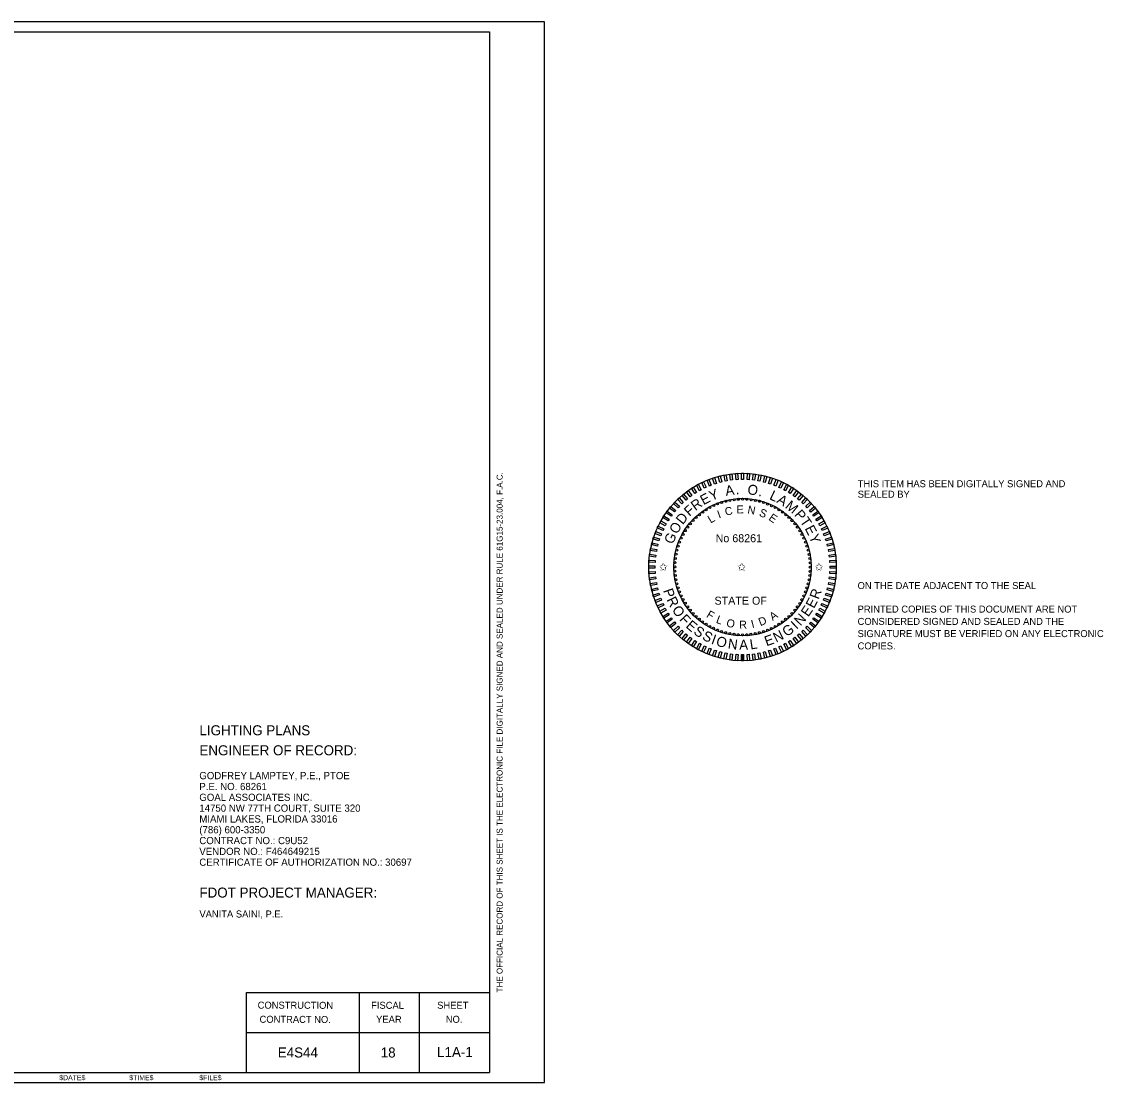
# Model space of a CAD drawing. Extents: x -820.2 to -798.1, y -2199.1 to -2182.2.
# Drawn here: x -808.95 to -798.14, y -2199.12 to -2188.52 of the extents above; entities that cross this region are included whole.
import ezdxf

# ---------------------------------------------------------------- set-up
doc = ezdxf.new("R2010")
doc.units = 0
for name, color, linetype in [('Logo_dp', 7, 'Continuous'), ('NonPlottingEle_dp', 7, 'Continuous'), ('PlotBorder_dp', 7, 'Continuous'), ('SheetBorder_dp', 7, 'Continuous'), ('SheetLines_dp', 7, 'Continuous'), ('TextLabel', 7, 'Continuous'), ('TextMinor', 7, 'Continuous'), ('TextMisc', 7, 'Continuous'), ('TextNotes', 7, 'Continuous')]:
    doc.layers.add(name, color=color, linetype=linetype)

msp = doc.modelspace()

# ---------------------------------------------------------------- linework, layer by layer
at = {"layer": 'Logo_dp'}
for p, q in [((-801.759, -2194.911), (-801.759, -2194.849)), ((-801.749, -2194.911), (-801.749, -2194.849)), ((-801.739, -2194.911), (-801.739, -2194.848))]:
    msp.add_line(p, q, dxfattribs=at)
for points in [[(-801.849, -2193.104), (-801.869, -2193.107), (-801.876, -2193.045), (-801.856, -2193.042)], [(-801.794, -2193.1), (-801.814, -2193.101), (-801.818, -2193.039), (-801.798, -2193.037)], [(-801.739, -2193.098), (-801.759, -2193.098), (-801.759, -2193.036), (-801.739, -2193.036)], [(-801.684, -2193.101), (-801.704, -2193.1), (-801.7, -2193.037), (-801.68, -2193.039)], [(-801.629, -2193.107), (-801.649, -2193.104), (-801.641, -2193.042), (-801.621, -2193.045)], [(-802.162, -2193.202), (-802.179, -2193.212), (-802.209, -2193.157), (-802.192, -2193.147)], [(-802.112, -2193.177), (-802.131, -2193.186), (-802.157, -2193.13), (-802.139, -2193.121)], [(-802.062, -2193.156), (-802.08, -2193.164), (-802.103, -2193.106), (-802.085, -2193.098)], [(-802.01, -2193.138), (-802.029, -2193.144), (-802.048, -2193.085), (-802.029, -2193.079)], [(-801.957, -2193.123), (-801.976, -2193.128), (-801.992, -2193.068), (-801.972, -2193.063)], [(-801.903, -2193.112), (-801.923, -2193.116), (-801.934, -2193.055), (-801.915, -2193.051)], [(-801.575, -2193.116), (-801.595, -2193.112), (-801.583, -2193.051), (-801.563, -2193.055)], [(-801.522, -2193.129), (-801.541, -2193.124), (-801.526, -2193.063), (-801.506, -2193.068)], [(-801.469, -2193.144), (-801.488, -2193.138), (-801.469, -2193.079), (-801.45, -2193.085)], [(-801.417, -2193.164), (-801.436, -2193.156), (-801.413, -2193.098), (-801.394, -2193.106)], [(-801.367, -2193.186), (-801.385, -2193.178), (-801.359, -2193.121), (-801.341, -2193.13)], [(-801.319, -2193.212), (-801.336, -2193.202), (-801.306, -2193.147), (-801.288, -2193.157)], [(-802.299, -2193.293), (-802.314, -2193.306), (-802.354, -2193.258), (-802.339, -2193.245)], [(-802.255, -2193.26), (-802.271, -2193.271), (-802.308, -2193.221), (-802.292, -2193.209)], [(-802.209, -2193.229), (-802.226, -2193.24), (-802.26, -2193.187), (-802.243, -2193.177)], [(-801.272, -2193.24), (-801.289, -2193.229), (-801.255, -2193.177), (-801.238, -2193.187)], [(-801.226, -2193.272), (-801.243, -2193.26), (-801.206, -2193.209), (-801.19, -2193.221)], [(-801.183, -2193.306), (-801.199, -2193.293), (-801.159, -2193.245), (-801.144, -2193.258)], [(-802.417, -2193.408), (-802.43, -2193.423), (-802.478, -2193.384), (-802.465, -2193.368)], [(-802.38, -2193.367), (-802.394, -2193.382), (-802.439, -2193.339), (-802.425, -2193.324)], [(-802.341, -2193.329), (-802.355, -2193.343), (-802.398, -2193.297), (-802.383, -2193.283)], [(-801.143, -2193.343), (-801.157, -2193.329), (-801.115, -2193.283), (-801.1, -2193.297)], [(-801.104, -2193.382), (-801.118, -2193.367), (-801.072, -2193.324), (-801.059, -2193.339)], [(-801.068, -2193.424), (-801.081, -2193.408), (-801.033, -2193.368), (-801.02, -2193.384)], [(-802.482, -2193.496), (-802.493, -2193.513), (-802.546, -2193.48), (-802.535, -2193.463)], [(-802.451, -2193.451), (-802.463, -2193.467), (-802.513, -2193.431), (-802.501, -2193.414)], [(-801.035, -2193.467), (-801.047, -2193.451), (-800.996, -2193.414), (-800.985, -2193.431)], [(-801.005, -2193.513), (-801.016, -2193.496), (-800.963, -2193.463), (-800.952, -2193.48)], [(-802.536, -2193.592), (-802.545, -2193.61), (-802.601, -2193.583), (-802.593, -2193.565)], [(-802.511, -2193.543), (-802.521, -2193.561), (-802.575, -2193.531), (-802.566, -2193.513)], [(-800.977, -2193.561), (-800.987, -2193.543), (-800.932, -2193.513), (-800.923, -2193.531)], [(-800.953, -2193.61), (-800.961, -2193.592), (-800.905, -2193.565), (-800.896, -2193.584)], [(-802.578, -2193.693), (-802.584, -2193.713), (-802.644, -2193.693), (-802.637, -2193.674)], [(-802.559, -2193.642), (-802.566, -2193.661), (-802.624, -2193.638), (-802.617, -2193.619)], [(-800.932, -2193.661), (-800.939, -2193.642), (-800.881, -2193.619), (-800.874, -2193.638)], [(-800.914, -2193.713), (-800.92, -2193.694), (-800.86, -2193.674), (-800.854, -2193.694)], [(-802.607, -2193.8), (-802.61, -2193.819), (-802.672, -2193.808), (-802.668, -2193.788)], [(-802.594, -2193.746), (-802.599, -2193.766), (-802.659, -2193.75), (-802.654, -2193.731)], [(-800.899, -2193.766), (-800.904, -2193.746), (-800.843, -2193.731), (-800.838, -2193.75)], [(-800.888, -2193.82), (-800.891, -2193.8), (-800.83, -2193.788), (-800.826, -2193.808)], [(-802.622, -2193.908), (-802.623, -2193.929), (-802.685, -2193.925), (-802.684, -2193.904)], [(-802.616, -2193.854), (-802.618, -2193.874), (-802.68, -2193.866), (-802.678, -2193.846)], [(-800.88, -2193.874), (-800.882, -2193.854), (-800.82, -2193.846), (-800.818, -2193.866)], [(-800.875, -2193.929), (-800.876, -2193.909), (-800.814, -2193.905), (-800.813, -2193.925)], [(-802.624, -2193.963), (-802.624, -2193.984), (-802.686, -2193.984), (-802.686, -2193.963)], [(-802.623, -2194.018), (-802.622, -2194.038), (-802.684, -2194.042), (-802.685, -2194.022)], [(-800.876, -2194.039), (-800.875, -2194.018), (-800.813, -2194.022), (-800.814, -2194.043)], [(-800.874, -2193.984), (-800.874, -2193.964), (-800.812, -2193.964), (-800.812, -2193.984)], [(-802.618, -2194.073), (-802.616, -2194.093), (-802.678, -2194.101), (-802.68, -2194.081)], [(-802.61, -2194.127), (-802.607, -2194.147), (-802.668, -2194.159), (-802.672, -2194.139)], [(-800.891, -2194.147), (-800.888, -2194.128), (-800.826, -2194.139), (-800.83, -2194.159)], [(-800.882, -2194.093), (-800.88, -2194.073), (-800.818, -2194.081), (-800.82, -2194.101)], [(-802.599, -2194.181), (-802.594, -2194.201), (-802.655, -2194.216), (-802.66, -2194.197)], [(-802.584, -2194.234), (-802.578, -2194.253), (-802.637, -2194.273), (-802.644, -2194.254)], [(-800.92, -2194.254), (-800.914, -2194.234), (-800.854, -2194.254), (-800.861, -2194.273)], [(-800.904, -2194.201), (-800.899, -2194.181), (-800.838, -2194.197), (-800.844, -2194.217)], [(-802.566, -2194.286), (-802.559, -2194.305), (-802.617, -2194.328), (-802.624, -2194.309)], [(-802.545, -2194.337), (-802.536, -2194.355), (-802.593, -2194.382), (-802.602, -2194.363)], [(-800.962, -2194.355), (-800.953, -2194.337), (-800.896, -2194.364), (-800.905, -2194.382)], [(-800.939, -2194.305), (-800.932, -2194.286), (-800.874, -2194.309), (-800.881, -2194.328)], [(-802.521, -2194.386), (-802.511, -2194.404), (-802.566, -2194.434), (-802.575, -2194.416)], [(-802.493, -2194.434), (-802.482, -2194.451), (-802.535, -2194.484), (-802.546, -2194.467)], [(-801.016, -2194.451), (-801.005, -2194.434), (-800.952, -2194.467), (-800.963, -2194.484)], [(-800.987, -2194.404), (-800.977, -2194.386), (-800.923, -2194.416), (-800.932, -2194.434)], [(-802.463, -2194.48), (-802.451, -2194.496), (-802.502, -2194.533), (-802.513, -2194.516)], [(-802.43, -2194.523), (-802.417, -2194.539), (-802.465, -2194.579), (-802.478, -2194.563)], [(-801.081, -2194.539), (-801.068, -2194.524), (-801.02, -2194.563), (-801.033, -2194.579)], [(-801.047, -2194.496), (-801.035, -2194.48), (-800.985, -2194.516), (-800.997, -2194.533)], [(-802.394, -2194.565), (-802.38, -2194.58), (-802.426, -2194.623), (-802.439, -2194.608)], [(-802.355, -2194.604), (-802.341, -2194.618), (-802.383, -2194.664), (-802.398, -2194.65)], [(-802.315, -2194.641), (-802.299, -2194.654), (-802.339, -2194.702), (-802.354, -2194.689)], [(-801.199, -2194.654), (-801.184, -2194.641), (-801.144, -2194.689), (-801.159, -2194.702)], [(-801.157, -2194.618), (-801.143, -2194.605), (-801.1, -2194.65), (-801.115, -2194.664)], [(-801.118, -2194.58), (-801.104, -2194.565), (-801.059, -2194.608), (-801.073, -2194.623)], [(-802.272, -2194.675), (-802.255, -2194.687), (-802.292, -2194.738), (-802.308, -2194.726)], [(-802.226, -2194.707), (-802.209, -2194.718), (-802.243, -2194.77), (-802.26, -2194.76)], [(-802.179, -2194.735), (-802.162, -2194.745), (-802.192, -2194.8), (-802.21, -2194.79)], [(-802.131, -2194.761), (-802.113, -2194.77), (-802.139, -2194.826), (-802.157, -2194.817)], [(-801.386, -2194.77), (-801.367, -2194.761), (-801.341, -2194.818), (-801.359, -2194.826)], [(-801.336, -2194.745), (-801.319, -2194.736), (-801.289, -2194.79), (-801.306, -2194.8)], [(-801.289, -2194.718), (-801.272, -2194.707), (-801.238, -2194.76), (-801.255, -2194.771)], [(-801.243, -2194.687), (-801.227, -2194.676), (-801.19, -2194.726), (-801.206, -2194.738)], [(-802.081, -2194.783), (-802.062, -2194.791), (-802.085, -2194.849), (-802.104, -2194.841)], [(-802.029, -2194.803), (-802.01, -2194.809), (-802.029, -2194.868), (-802.048, -2194.862)], [(-801.976, -2194.819), (-801.957, -2194.824), (-801.972, -2194.884), (-801.992, -2194.879)], [(-801.923, -2194.831), (-801.903, -2194.835), (-801.915, -2194.896), (-801.935, -2194.892)], [(-801.869, -2194.84), (-801.849, -2194.843), (-801.857, -2194.905), (-801.877, -2194.902)], [(-801.814, -2194.846), (-801.794, -2194.847), (-801.798, -2194.91), (-801.818, -2194.909)], [(-801.759, -2194.849), (-801.739, -2194.849), (-801.739, -2194.911), (-801.759, -2194.911)], [(-801.704, -2194.847), (-801.684, -2194.846), (-801.68, -2194.909), (-801.7, -2194.91)], [(-801.649, -2194.843), (-801.629, -2194.84), (-801.622, -2194.902), (-801.642, -2194.905)], [(-801.595, -2194.835), (-801.575, -2194.831), (-801.563, -2194.893), (-801.583, -2194.896)], [(-801.541, -2194.824), (-801.522, -2194.819), (-801.506, -2194.879), (-801.526, -2194.884)], [(-801.488, -2194.809), (-801.469, -2194.803), (-801.45, -2194.862), (-801.469, -2194.868)], [(-801.436, -2194.791), (-801.418, -2194.783), (-801.395, -2194.841), (-801.413, -2194.849)]]:
    msp.add_lwpolyline(points, close=True, dxfattribs=at)
for centre in [(-802.075, -2193.38), (-802.037, -2193.36), (-801.998, -2193.343), (-801.958, -2193.329), (-801.917, -2193.317), (-801.875, -2193.308), (-801.833, -2193.301), (-801.791, -2193.297), (-801.748, -2193.296), (-801.706, -2193.297), (-801.664, -2193.301), (-801.621, -2193.308), (-801.58, -2193.317), (-801.539, -2193.329), (-801.499, -2193.344), (-801.46, -2193.361), (-801.422, -2193.38), (-802.212, -2193.479), (-802.18, -2193.451), (-802.147, -2193.425), (-802.112, -2193.401), (-801.386, -2193.402), (-801.35, -2193.426), (-801.317, -2193.452), (-801.285, -2193.48), (-802.297, -2193.575), (-802.271, -2193.541), (-802.242, -2193.509), (-801.255, -2193.51), (-801.227, -2193.542), (-801.201, -2193.576), (-802.362, -2193.685), (-802.342, -2193.647), (-802.321, -2193.61), (-801.177, -2193.611), (-801.155, -2193.648), (-801.136, -2193.686), (-802.405, -2193.805), (-802.393, -2193.764), (-802.379, -2193.724), (-801.119, -2193.725), (-801.105, -2193.765), (-801.093, -2193.806), (-802.421, -2193.888), (-802.414, -2193.846), (-801.083, -2193.847), (-801.077, -2193.889), (-802.426, -2193.973), (-802.425, -2193.93), (-802.425, -2194.016), (-801.073, -2193.932), (-801.073, -2194.017), (-801.072, -2193.974), (-802.421, -2194.058), (-802.415, -2194.1), (-801.084, -2194.101), (-801.077, -2194.059), (-802.405, -2194.141), (-802.393, -2194.182), (-802.379, -2194.222), (-801.119, -2194.223), (-801.105, -2194.183), (-801.093, -2194.143), (-802.362, -2194.261), (-802.343, -2194.299), (-802.321, -2194.336), (-801.177, -2194.337), (-801.156, -2194.3), (-801.136, -2194.262), (-802.297, -2194.371), (-802.271, -2194.405), (-802.243, -2194.437), (-801.256, -2194.438), (-801.227, -2194.406), (-801.201, -2194.372), (-802.213, -2194.467), (-802.181, -2194.495), (-802.148, -2194.521), (-802.112, -2194.545), (-802.076, -2194.567), (-801.423, -2194.567), (-801.386, -2194.546), (-801.351, -2194.522), (-801.318, -2194.496), (-801.286, -2194.468), (-802.038, -2194.586), (-801.999, -2194.603), (-801.959, -2194.618), (-801.918, -2194.63), (-801.876, -2194.639), (-801.834, -2194.646), (-801.792, -2194.65), (-801.749, -2194.651), (-801.707, -2194.65), (-801.665, -2194.646), (-801.623, -2194.639), (-801.581, -2194.63), (-801.54, -2194.618), (-801.5, -2194.604), (-801.461, -2194.587)]:
    msp.add_circle(centre, 0.01, dxfattribs=at)
at = {"layer": 'NonPlottingEle_dp'}
for radius in [0.937, 0.687]:
    msp.add_circle((-801.749, -2193.974), radius, dxfattribs=at)
at = {"layer": 'PlotBorder_dp'}
msp.add_lwpolyline([(-820.227, -2199.124), (-803.727, -2199.124), (-803.727, -2188.524), (-820.227, -2188.524)], close=True, dxfattribs=at)
at = {"layer": 'SheetBorder_dp'}
for p, q in [((-819.677, -2188.624), (-804.277, -2188.624)), ((-804.277, -2188.624), (-804.277, -2199.024)), ((-819.677, -2199.024), (-804.277, -2199.024))]:
    msp.add_line(p, q, dxfattribs=at)
at = {"layer": 'SheetLines_dp'}
for p, q in [((-806.708, -2198.224), (-804.277, -2198.224)), ((-806.708, -2199.024), (-806.708, -2198.224)), ((-805.577, -2199.024), (-805.577, -2198.224)), ((-804.977, -2199.024), (-804.977, -2198.224)), ((-806.708, -2198.624), (-804.277, -2198.624))]:
    msp.add_line(p, q, dxfattribs=at)

# ---------------------------------------------------------------- texts
at = {"layer": 'Logo_dp'}
for s, height, rotation, p in [('A', 0.1, 8.8088, (-801.914, -2193.263)), ('O', 0.1, 352.1877, (-801.704, -2193.245)), ('E', 0.1, 28.1055, (-802.139, -2193.357)), ('Y', 0.1, 21.0633, (-802.061, -2193.314)), ('.', 0.1, 1.0418, (-801.816, -2193.247)), ('.', 0.1, 343.5268, (-801.595, -2193.261)), ('L', 0.1, 334.6727, (-801.487, -2193.293)), ('A', 0.1, 328.4096, (-801.414, -2193.325)), ('F', 0.1, 42.3772, (-802.279, -2193.473)), ('R', 0.1, 35.9269, (-802.22, -2193.416)), ('C', 0.08, 12.2025, (-801.917, -2193.462)), ('E', 0.08, 0.4186, (-801.809, -2193.438)), ('N', 0.08, 349.2914, (-801.704, -2193.437)), ('M', 0.1, 320.6426, (-801.33, -2193.377)), ('D', 0.1, 50.8569, (-802.347, -2193.556)), ('L', 0.08, 30.4021, (-802.068, -2193.54)), ('I', 0.08, 20.0117, (-801.985, -2193.489)), ('S', 0.08, 337.0221, (-801.591, -2193.459)), ('E', 0.08, 325.8663, (-801.495, -2193.499)), ('P', 0.1, 311.1966, (-801.237, -2193.454)), ('T', 0.1, 304.4563, (-801.18, -2193.517)), ('O', 0.1, 59.5178, (-802.403, -2193.651)), ('E', 0.1, 297.6315, (-801.13, -2193.588)), ('G', 0.1, 68.0518, (-802.444, -2193.752)), ('Y', 0.1, 290.5893, (-801.087, -2193.667)), ('P', 0.1, 289.4055, (-802.544, -2194.208)), ('R', 0.1, 69.5134, (-800.989, -2194.303)), ('R', 0.1, 296.1458, (-802.511, -2194.3)), ('E', 0.1, 62.4712, (-801.035, -2194.394)), ('O', 0.1, 303.9671, (-802.459, -2194.4)), ('F', 0.1, 312.628, (-802.387, -2194.502)), ('F', 0.08, 328.7241, (-802.117, -2194.47)), ('A', 0.08, 34.4992, (-801.447, -2194.513)), ('N', 0.1, 47.1788, (-801.171, -2194.567)), ('E', 0.1, 55.4289, (-801.092, -2194.478)), ('E', 0.1, 319.0783, (-802.323, -2194.571)), ('L', 0.08, 339.2916, (-802.02, -2194.529)), ('O', 0.08, 349.6821, (-801.915, -2194.569)), ('R', 0.08, 2.3398, (-801.781, -2194.591)), ('I', 0.08, 14.2037, (-801.653, -2194.584)), ('D', 0.08, 22.0128, (-801.571, -2194.565)), ('G', 0.1, 35.1115, (-801.308, -2194.675)), ('I', 0.1, 43.6456, (-801.209, -2194.602)), ('S', 0.1, 326.1206, (-802.246, -2194.637)), ('S', 0.1, 333.193, (-802.16, -2194.693)), ('I', 0.1, 340.2654, (-802.069, -2194.738)), ('O', 0.1, 343.7986, (-802.021, -2194.756)), ('E', 0.1, 19.8191, (-801.509, -2194.767)), ('N', 0.1, 26.8614, (-801.413, -2194.731)), ('N', 0.1, 352.4595, (-801.9, -2194.788)), ('A', 0.1, 0.7097, (-801.782, -2194.801)), ('L', 0.1, 8.4767, (-801.669, -2194.798))]:
    msp.add_text(s, height=height, rotation=rotation, dxfattribs=at).set_placement(p)
for s, p in [('No 68261', (-802.018, -2193.726)), ('✩', (-802.584, -2194.011)), ('✩', (-801.799, -2194.011)), ('✩', (-801.027, -2194.011)), ('STATE OF', (-802.029, -2194.35))]:
    msp.add_text(s, height=0.08, dxfattribs=at).set_placement(p)
at = {"layer": 'TextLabel'}
for s, height, p in [('LIGHTING PLANS', 0.1, (-807.177, -2195.655)), ('ENGINEER OF RECORD:', 0.1, (-807.177, -2195.855)), ('GODFREY LAMPTEY, P.E., PTOE', 0.07202, (-807.178, -2196.094)), ('P.E. NO. 68261', 0.07202, (-807.178, -2196.203)), ('GOAL ASSOCIATES INC. ', 0.07202, (-807.178, -2196.311)), ('14750 NW 77TH COURT, SUITE 320', 0.07202, (-807.178, -2196.419)), ('MIAMI LAKES, FLORIDA 33016', 0.07202, (-807.178, -2196.527)), ('(786) 600-3350', 0.07202, (-807.178, -2196.635)), ('CONTRACT NO.: C9U52', 0.07202, (-807.178, -2196.743)), ('VENDOR NO.: F464649215', 0.07202, (-807.178, -2196.851)), ('CERTIFICATE OF AUTHORIZATION NO.: 30697', 0.07202, (-807.178, -2196.959)), ('E4S44', 0.1, (-806.394, -2198.875)), ('18', 0.1, (-805.365, -2198.875)), ('L1A-1', 0.1, (-804.802, -2198.871))]:
    msp.add_text(s, height=height, dxfattribs=at).set_placement(p)
at = {"layer": 'TextMinor'}
for s, p in [('$DATE$', (-808.578, -2199.102)), ('$TIME$', (-807.878, -2199.102)), ('$FILE$', (-807.178, -2199.102))]:
    msp.add_text(s, height=0.05, rotation=360, dxfattribs=at).set_placement(p)
at = {"layer": 'TextMisc'}
msp.add_text('THE OFFICIAL RECORD OF THIS SHEET IS THE ELECTRONIC FILE DIGITALLY SIGNED AND SEALED UNDER RULE 61G15-23.004, F.A.C.', height=0.06, rotation=90, dxfattribs=at).set_placement((-804.147, -2198.224))
for s, p in [('THIS ITEM HAS BEEN DIGITALLY SIGNED AND ', (-800.598, -2193.176)), ('SEALED BY', (-800.598, -2193.281)), ('ON THE DATE ADJACENT TO THE SEAL', (-800.599, -2194.194)), ('PRINTED COPIES OF THIS DOCUMENT ARE NOT ', (-800.599, -2194.429)), ('CONSIDERED SIGNED AND SEALED AND THE ', (-800.599, -2194.552)), ('SIGNATURE MUST BE VERIFIED ON ANY ELECTRONIC ', (-800.599, -2194.674)), ('COPIES.', (-800.599, -2194.797))]:
    msp.add_text(s, height=0.07, dxfattribs=at).set_placement(p)
at = {"layer": 'TextNotes'}
for s, height, p in [('FDOT PROJECT MANAGER:', 0.1, (-807.177, -2197.277)), ('VANITA SAINI, P.E.', 0.07, (-807.177, -2197.476))]:
    msp.add_text(s, height=height, dxfattribs=at).set_placement(p)
for s, p in [('CONSTRUCTION', (-806.595, -2198.387)), ('FISCAL', (-805.461, -2198.388)), ('SHEET', (-804.801, -2198.388)), ('CONTRACT NO.', (-806.576, -2198.528)), ('YEAR', (-805.411, -2198.528)), ('NO.', (-804.715, -2198.528))]:
    msp.add_text(s, height=0.07, rotation=359.8607, dxfattribs=at).set_placement(p)

doc.saveas('drawing.dxf')
